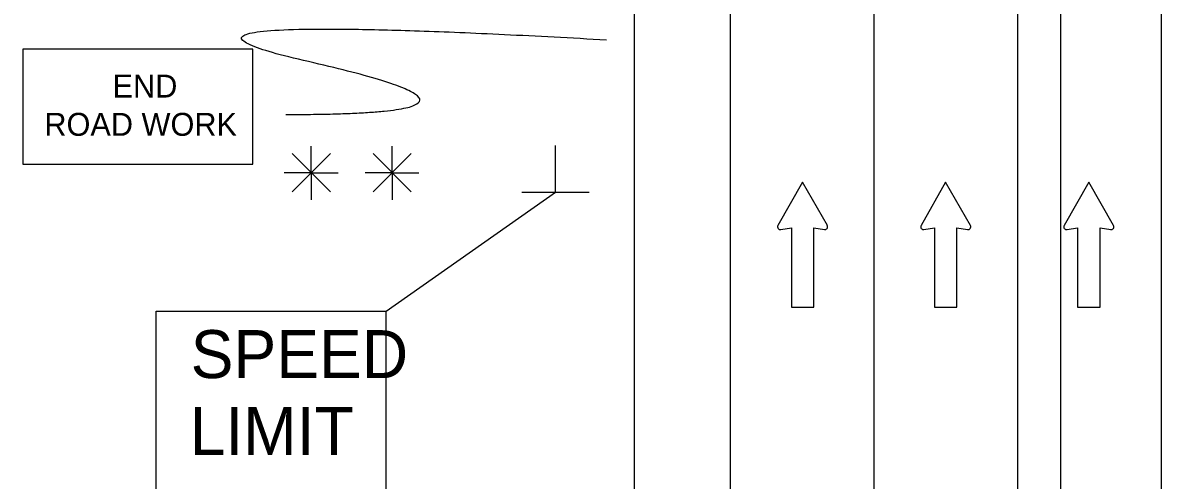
# Model space of a CAD drawing. Extents: x 16726 to 18479, y 5932 to 7023.
# Drawn here: x 16756.6 to 16946.7, y 6848.6 to 6924.9 of the extents above; entities that cross this region are included whole.
import ezdxf

# ---------------------------------------------------------------- set-up
doc = ezdxf.new("R2010")
doc.units = 0
for name, color, linetype in [('ALI_LEGAL_EX', 7, 'Continuous'), ('MT_SCRATCH_LEVEL_E', 7, 'Continuous'), ('PAVT_EDGE_EX', 7, 'Continuous'), ('TRAFFIC_SIGNS_PR', 7, 'Continuous'), ('TYPICAL_TEXT_DIMEN_PR', 7, 'Continuous')]:
    doc.layers.add(name, color=color, linetype=linetype)

msp = doc.modelspace()

# ---------------------------------------------------------------- linework, layer by layer
at = {"layer": 'ALI_LEGAL_EX'}
for p, q in [((16898.69, 7022.86), (16898.69, 6323.13)), ((16922.69, 7022.86), (16922.69, 6323.13)), ((16946.69, 7022.86), (16946.69, 6323.13)), ((16929.88, 7005.57), (16929.88, 6176.39))]:
    msp.add_line(p, q, dxfattribs=at)
for points in [[(16898.69, 6882.86), (16898.69, 6857.86)], [(16922.69, 6882.86), (16922.69, 6857.86)], [(16946.69, 6882.86), (16946.69, 6857.86)]]:
    msp.add_lwpolyline(points, dxfattribs=at)
at = {"layer": 'MT_SCRATCH_LEVEL_E'}
for p, q in [((16886.79, 6898.33), (16882.68, 6891.09)), ((16890.94, 6891.09), (16886.79, 6898.33)), ((16910.69, 6898.33), (16906.58, 6891.09)), ((16914.84, 6891.09), (16910.69, 6898.33)), ((16934.6, 6898.33), (16930.49, 6891.09)), ((16938.74, 6891.09), (16934.6, 6898.33)), ((16883.16, 6890.41), (16884.94, 6890.72)), ((16884.94, 6890.72), (16884.94, 6877.46)), ((16888.68, 6877.46), (16888.68, 6890.72)), ((16888.68, 6890.72), (16890.46, 6890.41)), ((16907.06, 6890.41), (16908.84, 6890.72)), ((16908.84, 6890.72), (16908.84, 6877.46)), ((16912.58, 6877.46), (16912.58, 6890.72)), ((16912.58, 6890.72), (16914.36, 6890.41)), ((16930.97, 6890.41), (16932.74, 6890.72)), ((16932.74, 6890.72), (16932.74, 6877.46)), ((16936.49, 6877.46), (16936.49, 6890.72)), ((16936.49, 6890.72), (16938.26, 6890.41)), ((16884.94, 6877.46), (16888.68, 6877.46)), ((16908.84, 6877.46), (16912.58, 6877.46)), ((16932.74, 6877.46), (16936.49, 6877.46))]:
    msp.add_line(p, q, dxfattribs=at)
for centre, start, end in [((16883.09, 6890.87), 150.4248, 279.9638), ((16890.53, 6890.87), 260.0362, 29.7731), ((16906.99, 6890.87), 150.4248, 279.9638), ((16914.43, 6890.87), 260.0362, 29.7731), ((16930.89, 6890.87), 150.4248, 279.9638), ((16938.33, 6890.87), 260.0362, 29.7731)]:
    msp.add_arc(centre, 0.463, start, end, dxfattribs=at)
at = {"layer": 'PAVT_EDGE_EX'}
for p, q in [((16858.69, 6927.61), (16858.69, 6215.05)), ((16874.69, 6927.61), (16874.69, 6215.05))]:
    msp.add_line(p, q, dxfattribs=at)
at = {"layer": 'TRAFFIC_SIGNS_PR'}
for p, q in [((16778.85, 6876.77), (16817.3, 6876.77)), ((16778.85, 6828.7), (16778.85, 6876.77)), ((16817.3, 6828.7), (16817.3, 6876.77))]:
    msp.add_line(p, q, dxfattribs=at)
msp.add_lwpolyline([(16756.59, 6901.32), (16794.99, 6901.32), (16794.99, 6920.52), (16756.59, 6920.52)], close=True, dxfattribs=at)
msp.add_open_spline([(16800.52, 6909.62), (16843.03, 6909.62), (16766.51, 6927.04), (16854.05, 6922.1)], degree=2, dxfattribs=at)
at = {"layer": 'TYPICAL_TEXT_DIMEN_PR'}
for p, q in [((16801.58, 6903.08), (16807.96, 6896.7)), ((16807.96, 6903.08), (16801.58, 6896.7)), ((16804.77, 6899.89), (16804.77, 6904.35)), ((16815.09, 6903.08), (16821.46, 6896.7)), ((16821.46, 6903.08), (16815.09, 6896.7)), ((16818.28, 6899.89), (16818.28, 6904.35)), ((16845.57, 6896.64), (16845.57, 6904.42)), ((16804.77, 6899.89), (16800.24, 6899.89)), ((16804.77, 6899.89), (16807.96, 6899.89)), ((16804.77, 6899.89), (16809.25, 6899.89)), ((16804.77, 6899.89), (16804.77, 6895.39)), ((16818.28, 6899.89), (16813.74, 6899.89)), ((16818.28, 6899.89), (16821.46, 6899.89)), ((16818.28, 6899.89), (16822.75, 6899.89)), ((16818.28, 6899.89), (16818.28, 6895.39)), ((16817.25, 6876.77), (16845.57, 6896.64)), ((16839.94, 6896.64), (16851.19, 6896.64))]:
    msp.add_line(p, q, dxfattribs=at)

# ---------------------------------------------------------------- texts
at = {"layer": 'TRAFFIC_SIGNS_PR'}
for s, height, p in [('END', 3.831, (16771.59, 6912.45)), ('ROAD WORK', 3.831, (16760.2, 6906.06)), ('SPEED', 8.01, (16784.63, 6865.61)), ('LIMIT', 8.01, (16784.47, 6852.8))]:
    msp.add_text(s, height=height, dxfattribs=at).set_placement(p)

doc.saveas('drawing.dxf')
